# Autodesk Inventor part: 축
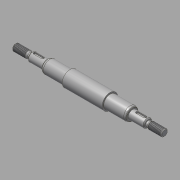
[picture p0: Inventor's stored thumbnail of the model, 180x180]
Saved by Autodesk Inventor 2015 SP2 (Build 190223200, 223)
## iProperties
Created: 2015-11
Part Number: 축
Material: 강철, 연강
Document SubType Name: Modeling
Designer: mduedu
Density: 1 g/cm^3
Appearance: 강철
Author: mduedu
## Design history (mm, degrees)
sketch "스케치1"
  geometry: L1 (-86, 0)-(86, 0); L2 (-86, 0)-(-86, 4); L3 (-86, 4)-(-70.732, 4); L4 (-70.732, 4)-(-69, 3); L5 (-69, 3)-(-67, 3); L6 (-67, 3)-(-67, 5); L7 (-67, 5)-(-49, 5); L8 (-49, 5)-(-49, 6.55); L9 (-47.355, 7.5)-(-23, 7.5); L10 (-23, 7.5)-(-23, 9); L11 (0, 0)-(0, 9); L12 (86, 4)-(70.732, 4); L13 (70.732, 4)-(69, 3); L14 (69, 3)-(67, 3); L15 (67, 3)-(67, 5); L16 (67, 5)-(49, 5); L17 (23, 7.5)-(23, 9); L18 (86, 0)-(86, 4); L19 (-23, 9)-(23, 9); L20 (-49, 6.55)-(-47.355, 7.5); L21 (47.355, 7.5)-(23, 7.5); L22 (49, 6.55)-(47.355, 7.5); L23 (49, 5)-(49, 6.55); 1 further point
  constraints: 46 end point, 10 symmetric about line, 6 perpendicular, 5 parallel, 2 midpoint, 1 coincident, 1 horizontal
  dimensions: "d0" = 172 distance of L1.start L1.end (derived); "d1" = 8 diameter of L3 L1; "d2" = 30 deg angle of L4 L5; "d3" = 6 diameter of L5 L1; "d4" = 10 diameter of L7 L1; "d5" = 15 diameter of L9 L1; "d6" = 18 diameter of L19 L1; "d8" = 18 distance of L6.end L7.end; "d9" = 46 distance of L10.end L17.end; "d10" = 2 distance of L4.end L5.end; "d11" = 17 distance from line of L4.end L2; "d16" = 13.1 diameter of L8.end L1; "d17" = 30 deg angle of L20 L9; "d18" = 26 distance between parallel lines of L10 L8
revolve "회전1" sketch "스케치1" stored, may be unused: angle "d12" = 90 deg
chamfer "모따기1" distance "d13" = 1; stored, may be unused: second distance "d14" = 2, angle "d15" = 45 deg
fillet "모깎기1" dims "d19" = 4, "d20" = 0.5
node "작업 평면1"
sketch "스케치2" dims "d23" = 12
  geometry: L1 (-5.5, 1.5)-(3.5, 1.5); L2 (3.5, 1.5)-(3.5, -1.5); L3 (3.5, -1.5)-(-5.5, -1.5); L4 (-5.5, -1.5)-(-5.5, 1.5); L5 (-9, -4)-(-9, 4) reference; 3 further points
  constraints: 8 end point, 2 midpoint, 2 parallel, 2 vertical alignment, 1 horizontal, 1 perpendicular, 4 other
  dimensions: "d21" = 3 distance between parallel lines of L3 L1; "d24" = 2 dimension on L5
extrude "돌출1" cut sketch "스케치2" distance "d25" = 1.8; taper "d26" = 0 deg
feature "스레드1" dims "d27" = 10, "d28" = 0
feature "스레드2" dims "d29" = 10, "d30" = 0
chamfer "모따기2" distance "d31" = 1; stored, may be unused: second distance "d32" = 2, angle "d33" = 45 deg
fillet "모깎기2" dims "d34" = 0.3
node "솔리드1"
mirror "대칭1"
